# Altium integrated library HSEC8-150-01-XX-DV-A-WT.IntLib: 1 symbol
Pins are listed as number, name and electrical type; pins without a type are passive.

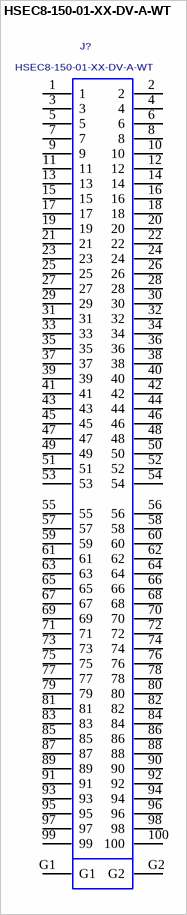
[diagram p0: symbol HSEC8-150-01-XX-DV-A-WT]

## HSEC8-150-01-XX-DV-A-WT
designator J?
0.8MM HIGH SPEED ASSEMBLY, WELD TAB OPTION.; MANUFACTURER: SAMTEC
footprint HSEC8-150-01-XX-DV-A-WT
pins: 1, 2, 3, 4, 5, 6, 7, 8, 9, 10, 11, 12, 13, 14, 15, 16, 17, 18, 19, 20, 21, 22, 23, 24, 25, 26, 27, 28, 29, 30, 31, 32, 33, 34, 35, 36, 37, 38, 39, 40, 41, 42, 43, 44, 45, 46, 47, 48, 49, 50, 51, 52, 53, 54, 55, 56, 57, 58, 59, 60, 61, 62, 63, 64, 65, 66, 67, 68, 69, 70, 71, 72, 73, 74, 75, 76, 77, 78, 79, 80, 81, 82, 83, 84, 85, 86, 87, 88, 89, 90, 91, 92, 93, 94, 95, 96, 97, 98, 99, 100, G1, G2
